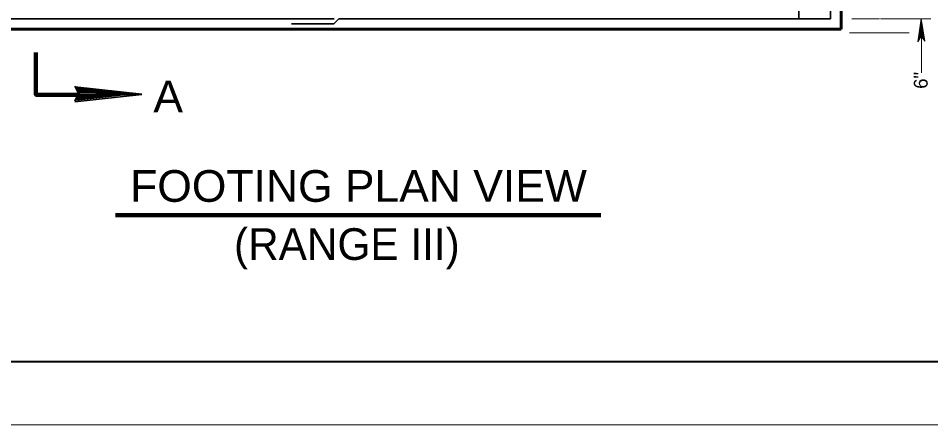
# Model space of a CAD drawing. Extents: x 144 to 252, y 360 to 425.
# Drawn here: x 160.9 to 182.53, y 360.42 to 370.05 of the extents above; entities that cross this region are included whole.
import ezdxf
from ezdxf.enums import TextEntityAlignment as Align

# ---------------------------------------------------------------- set-up
doc = ezdxf.new("R2010")
doc.units = 0
doc.header["$LTSCALE"] = 0.13
for name, color, linetype, lineweight in [('1', 7, 'Continuous', 40), ('14', 7, 'Continuous', 13), ('16', 7, 'Continuous', 13), ('3', 7, 'Continuous', 13)]:
    doc.layers.add(name, color=color, linetype=linetype, lineweight=lineweight)

msp = doc.modelspace()

# ---------------------------------------------------------------- linework, layer by layer
at = {"layer": '1', "lineweight": 60}
for p, q in [((180.4041, 369.7844), (180.4041, 374.1902)), ((180.4041, 369.7844), (180.4041, 372.362)), ((180.4041, 369.7844), (180.4041, 372.362)), ((156.4041, 369.7844), (180.4041, 369.7844)), ((156.4041, 369.7844), (180.4041, 369.7844)), ((156.4041, 369.7844), (180.4041, 369.7844)), ((156.4041, 369.7844), (180.4041, 369.7844)), ((156.4041, 369.7844), (180.4041, 369.7844))]:
    msp.add_line(p, q, dxfattribs=at)
at = {"layer": '1', "lineweight": 35}
for p, q in [((179.4041, 372.362), (179.4041, 370.0344)), ((156.6541, 370.0344), (168.3923, 370.0344)), ((168.4963, 370.0344), (180.1541, 370.0344)), ((162.2384, 368.4237), (163.8284, 368.2467)), ((162.2744, 368.3818), (163.4564, 368.2527)), ((162.2774, 368.4087), (163.4624, 368.2797)), ((162.2774, 368.4027), (163.4624, 368.2767)), ((162.2774, 368.3967), (163.4564, 368.2647)), ((162.2804, 368.4147), (163.4624, 368.2858)), ((163.8314, 368.2437), (162.2414, 368.0668)), ((162.2414, 368.2407), (163.8314, 368.2407)), ((162.2714, 368.1597), (163.3754, 368.2797)), ((162.2744, 368.1418), (163.3754, 368.2618)), ((162.2774, 368.1237), (163.3814, 368.2437)), ((162.2804, 368.1087), (163.3844, 368.2287))]:
    msp.add_line(p, q, dxfattribs=at)
at = {"layer": '1', "lineweight": 13}
for p, q in [((181.3125, 370.034), (180.6607, 370.034)), ((182.5277, 370.034), (181.3369, 370.034)), ((182.3068, 369.9186), (182.3068, 368.7553)), ((182.3109, 369.974), (182.3109, 369.6687)), ((182.0191, 369.7028), (180.6024, 369.7028)), ((143.8112, 360.4183), (251.8112, 360.4183))]:
    msp.add_line(p, q, dxfattribs=at)
at = {"layer": '1'}
msp.add_line((149.8112, 361.9183), (250.3172, 361.9183), dxfattribs=at)
msp.add_lwpolyline([(250.3172, 361.9183), (250.3172, 423.9913), (149.8112, 423.9913), (149.8112, 361.9183), (230.3642, 361.9183)], dxfattribs=at)
at = {"layer": '1', "lineweight": 60}
msp.add_lwpolyline([(156.4041, 379.7844), (180.4041, 379.7844), (180.4041, 369.7844)], dxfattribs=at)
at = {"layer": '1', "lineweight": 35}
for points in [[(180.1541, 375.7844), (180.1541, 372.362), (180.1541, 370.0344)], [(162.2444, 368.0817), (162.3284, 368.2618), (162.2444, 368.4357)], [(162.3524, 368.2797), (163.0604, 368.2887), (163.0574, 368.2707), (162.9194, 368.2797), (162.3524, 368.2887), (162.8084, 368.3037), (162.3314, 368.3127), (162.6674, 368.3247), (162.3194, 368.3427), (162.8624, 368.3007), (163.5704, 368.2707), (163.4234, 368.2317), (163.6184, 368.2498), (162.3524, 368.2437), (162.7214, 368.2197), (162.3314, 368.2197), (163.1414, 368.2767), (162.3254, 368.1867), (162.3554, 368.2767), (162.2894, 368.3877), (162.3254, 368.3637), (162.3554, 368.3007), (162.3974, 368.3187), (162.3704, 368.3698), (162.3464, 368.2557), (162.3134, 368.1867), (162.2804, 368.1087)]]:
    msp.add_lwpolyline(points, dxfattribs=at)
at = {"layer": '14', "lineweight": 106}
msp.add_line((163.2086, 365.3818), (174.7086, 365.3818), dxfattribs=at)
at = {"layer": '16', "lineweight": 106}
msp.add_lwpolyline([(161.3212, 369.2324), (161.3212, 368.2324), (162.3212, 368.2324)], dxfattribs=at)
at = {"layer": '3'}
for p, q in [((182.2248, 369.4911), (182.3026, 370.0398)), ((182.2283, 369.4971), (182.3032, 370.0254)), ((182.2303, 369.5006), (182.3032, 370.0146)), ((182.233, 369.5052), (182.3032, 370.0002)), ((182.2354, 369.5093), (182.3032, 369.9874)), ((182.2354, 369.5093), (182.3032, 369.9874)), ((182.2376, 369.5129), (182.3032, 369.9761)), ((182.2403, 369.5175), (182.3032, 369.9617)), ((182.2427, 369.5216), (182.3032, 369.9489)), ((182.2452, 369.526), (182.3032, 369.9352)), ((182.2477, 369.5304), (182.3032, 369.9213)), ((182.2502, 369.5347), (182.3032, 369.9081)), ((182.2529, 369.5392), (182.3032, 369.8942)), ((182.2552, 369.5432), (182.3032, 369.8816)), ((182.2574, 369.5469), (182.3032, 369.8702)), ((182.2602, 369.5519), (182.3032, 369.8545)), ((182.3026, 370.0398), (182.3918, 369.5022)), ((182.3026, 369.6244), (182.3026, 370.0398)), ((182.3032, 370.0254), (182.3895, 369.5054)), ((182.3032, 370.0146), (182.3872, 369.5087)), ((182.3032, 370.0002), (182.384, 369.5129)), ((182.3032, 369.9874), (182.3813, 369.5167)), ((182.3032, 369.9761), (182.3789, 369.52)), ((182.3032, 369.9617), (182.3757, 369.5242)), ((182.3032, 369.9489), (182.373, 369.528)), ((182.3032, 369.9352), (182.3701, 369.5321)), ((182.3032, 369.9213), (182.3671, 369.5362)), ((182.3032, 369.9081), (182.3642, 369.5401)), ((182.3032, 369.8942), (182.3612, 369.5442)), ((182.3032, 369.8816), (182.3586, 369.5479)), ((182.3032, 369.8702), (182.3561, 369.5513)), ((182.3032, 369.8545), (182.3527, 369.5559)), ((182.2629, 369.5563), (182.3032, 369.8407)), ((182.2652, 369.5603), (182.3022, 369.8211)), ((182.2671, 369.5635), (182.3038, 369.8227)), ((182.2697, 369.5679), (182.3038, 369.8087)), ((182.2722, 369.5722), (182.3038, 369.7956)), ((182.273, 369.5737), (182.3032, 369.7865)), ((182.2752, 369.5776), (182.3032, 369.7745)), ((182.2779, 369.582), (182.3032, 369.7607)), ((182.2807, 369.587), (182.3032, 369.745)), ((182.2832, 369.5911), (182.3032, 369.7324)), ((182.2857, 369.5953), (182.3032, 369.7192)), ((182.2879, 369.5992), (182.3032, 369.7072)), ((182.2906, 369.6038), (182.3032, 369.6927)), ((182.2932, 369.6082), (182.3032, 369.6788)), ((182.2955, 369.6123), (182.3032, 369.6662)), ((182.2986, 369.6176), (182.3022, 369.6427)), ((182.3002, 369.6202), (182.3032, 369.6415)), ((182.3032, 369.8407), (182.3498, 369.56)), ((182.3032, 369.7865), (182.3381, 369.576)), ((182.3032, 369.7745), (182.3355, 369.5796)), ((182.3032, 369.7607), (182.3325, 369.5837)), ((182.3032, 369.745), (182.3293, 369.5883)), ((182.3032, 369.7324), (182.3265, 369.592)), ((182.3032, 369.7192), (182.3237, 369.5959)), ((182.3032, 369.7072), (182.321, 369.5995)), ((182.3032, 369.6927), (182.318, 369.6037)), ((182.3032, 369.6788), (182.315, 369.6079)), ((182.3032, 369.6662), (182.3123, 369.6116)), ((182.3032, 369.6529), (182.3094, 369.6155)), ((182.3032, 369.6415), (182.307, 369.6189)), ((182.3038, 369.8227), (182.3467, 369.5643)), ((182.3038, 369.8087), (182.3437, 369.5684)), ((182.3038, 369.7956), (182.3408, 369.5722)), ((182.3028, 369.6247), (182.2248, 369.4911)), ((182.3918, 369.5022), (182.3028, 369.6247)), ((182.3032, 369.6313), (182.3047, 369.6219))]:
    msp.add_line(p, q, dxfattribs=at)
at = {"layer": '3', "lineweight": 35}
msp.add_lwpolyline([(168.4963, 370.0344), (168.3785, 369.9166), (167.3785, 369.9166)], dxfattribs=at)

# ---------------------------------------------------------------- texts
at = {"layer": '14', "width": 1.05}
msp.add_text('FOOTING PLAN VIEW', height=0.75, dxfattribs=at).set_placement((168.9648, 365.6982), align=Align.CENTER)
at = {"layer": '14'}
msp.add_text('(RANGE III)', height=0.75, dxfattribs=at).set_placement((168.6896, 364.3217), align=Align.CENTER)
at = {"layer": '16', "width": 1.05}
msp.add_text('A', height=0.75, dxfattribs=at).set_placement((164.1028, 367.8185))
at = {"layer": '16'}
msp.add_text('6"', height=0.3281, rotation=90, dxfattribs=at).set_placement((182.4561, 368.7743), align=Align.RIGHT)

doc.saveas('drawing.dxf')
